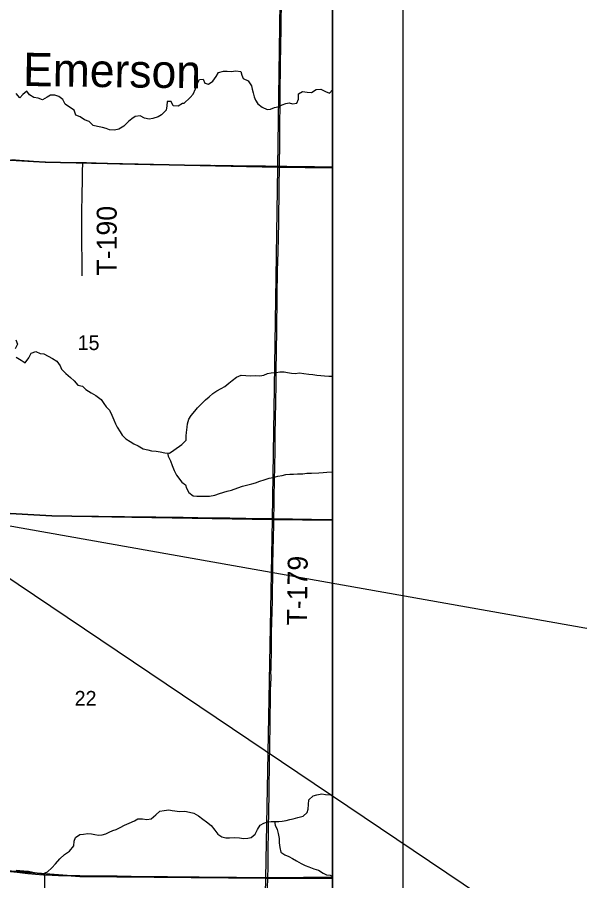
# Model space of a CAD drawing. Extents: x 0 to 34, y 0 to 22.
# Drawn here: x 8.451 to 9.252, y 18.765 to 19.994 of the extents above; entities that cross this region are included whole.
import ezdxf

# ---------------------------------------------------------------- set-up
doc = ezdxf.new("R2010")
doc.units = 0
for name, color, linetype in [('GM_X_Corporation', 7, 'Continuous'), ('GM_X_County_Road', 7, 'Continuous'), ('GM_X_Minor_River', 7, 'Continuous'), ('GM_X_Minor_River_Text', 7, 'Continuous'), ('GM_X_Section_Text', 7, 'Continuous'), ('GM_X_Township_Road', 7, 'Continuous'), ('GM_X_Township_Road_Text', 7, 'Continuous'), ('SH_Data', 7, 'Continuous'), ('SH_Text', 7, 'Continuous')]:
    doc.layers.add(name, color=color, linetype=linetype)

msp = doc.modelspace()

# ---------------------------------------------------------------- linework, layer by layer
at = {"layer": 'GM_X_Corporation'}
for points in [[(8.9, 14.1), (8.9, 20.772)], [(8.9, 17.776), (8.9, 20.772)]]:
    msp.add_lwpolyline(points, dxfattribs=at)
for points in [[(8.2996, 20.3033), (8.5044, 20.2865), (8.8288, 20.2829), (8.8217, 19.7804), (8.4905, 19.7876), (8.2906, 19.7989)], [(8.9, 19.7793), (8.9, 20.2818), (8.8288, 20.2829), (8.8217, 19.7804)], [(8.2906, 19.7989), (8.4905, 19.7876), (8.8217, 19.7804), (8.8138, 19.279), (8.5, 19.2839), (8.2875, 19.2957)], [(8.9, 19.2778), (8.9, 19.7793), (8.8217, 19.7804), (8.8138, 19.279)], [(8.2875, 19.2957), (8.5, 19.2839), (8.8138, 19.279), (8.8044, 18.7684), (8.5402, 18.7705), (8.2902, 18.7899)], [(8.9, 18.7679), (8.9, 19.2778), (8.8138, 19.279), (8.8044, 18.7684)], [(8.2902, 18.7899), (8.5402, 18.7705), (8.8044, 18.7684), (8.794, 18.271), (8.5238, 18.284), (8.2939, 18.2862)], [(8.9, 18.2696), (8.9, 18.7679), (8.8044, 18.7684), (8.794, 18.271)]]:
    msp.add_lwpolyline(points, close=True, dxfattribs=at)
at = {"layer": 'GM_X_County_Road'}
for points in [[(8.2874, 19.297), (8.3005, 19.2963), (8.3111, 19.2956), (8.3378, 19.294), (8.3989, 19.2902), (8.4417, 19.2875), (8.4867, 19.2848), (8.4988, 19.2844), (8.5215, 19.284), (8.5668, 19.2834), (8.6038, 19.2831), (8.6365, 19.2826), (8.6483, 19.2825), (8.6688, 19.2822), (8.6874, 19.282), (8.708, 19.2817), (8.7341, 19.2814), (8.7536, 19.2812), (8.7763, 19.2809), (8.8133, 19.2803), (8.8164, 19.2803)], [(8.8164, 19.2803), (8.8702, 19.2793), (8.8885, 19.279), (8.9, 19.2789)]]:
    msp.add_lwpolyline(points, dxfattribs=at)
at = {"layer": 'GM_X_Minor_River'}
for points in [[(8.6881, 19.8709), (8.6971, 19.8795), (8.7017, 19.8846), (8.705, 19.8922), (8.7073, 19.8992), (8.7103, 19.9054), (8.7156, 19.906), (8.7179, 19.8999), (8.7235, 19.8987), (8.7294, 19.9031), (8.7342, 19.9097), (8.7376, 19.9152), (8.7448, 19.9174), (8.7497, 19.9174), (8.7554, 19.9168), (8.7624, 19.9177), (8.7694, 19.9166), (8.7706, 19.9116), (8.7728, 19.9069), (8.78, 19.9034), (8.7845, 19.8964), (8.7854, 19.8916), (8.7869, 19.8861), (8.7884, 19.8808), (8.7901, 19.8761), (8.7937, 19.8705), (8.7999, 19.8658), (8.8067, 19.8627), (8.8118, 19.8632), (8.8175, 19.8653), (8.8223, 19.8664), (8.8285, 19.869), (8.8333, 19.8713), (8.8382, 19.8722), (8.8431, 19.8707), (8.8492, 19.8716), (8.8515, 19.8773), (8.8517, 19.8847), (8.8574, 19.8884), (8.864, 19.8875), (8.8701, 19.8869), (8.8767, 19.891), (8.8834, 19.8916), (8.89, 19.8883), (8.8958, 19.886), (8.9, 19.8906)], [(8.6881, 19.8709), (8.6864, 19.8709), (8.6801, 19.8672), (8.6731, 19.8676), (8.6701, 19.8742), (8.6642, 19.8739), (8.6638, 19.8678), (8.663, 19.8614), (8.6564, 19.855), (8.6516, 19.852), (8.6439, 19.8496), (8.6389, 19.849), (8.6323, 19.8502), (8.6259, 19.8536), (8.6189, 19.8524), (8.6141, 19.8492), (8.6092, 19.8454), (8.6025, 19.8388), (8.5955, 19.8348), (8.5893, 19.8332), (8.5823, 19.8338), (8.5774, 19.8357), (8.5723, 19.8371), (8.5651, 19.8384), (8.5589, 19.8396), (8.5532, 19.8457), (8.5466, 19.848), (8.5404, 19.852), (8.5345, 19.8543), (8.5317, 19.8614), (8.5255, 19.866), (8.5191, 19.8702), (8.5158, 19.8768), (8.5103, 19.881), (8.5042, 19.8828), (8.4982, 19.883), (8.4933, 19.8802), (8.487, 19.8764), (8.4806, 19.8789), (8.4743, 19.8797), (8.4683, 19.8837), (8.4644, 19.8885), (8.4589, 19.884), (8.4545, 19.8791), (8.4494, 19.8854)], [(8.4487, 19.5347), (8.4513, 19.5283), (8.4477, 19.5218)], [(8.4495, 19.5099), (8.4563, 19.5055), (8.4623, 19.5018), (8.4671, 19.5088), (8.4705, 19.5156), (8.4773, 19.5181), (8.4836, 19.5154), (8.4889, 19.5148), (8.5009, 19.5083), (8.5073, 19.5044), (8.5118, 19.4976)], [(8.5118, 19.4976), (8.5141, 19.4928), (8.5201, 19.4865), (8.5269, 19.4812), (8.5318, 19.4764), (8.537, 19.4701), (8.5438, 19.4686), (8.5487, 19.4638), (8.5563, 19.4592), (8.5629, 19.4556), (8.5702, 19.4495), (8.5743, 19.4439), (8.5777, 19.4392), (8.5822, 19.4344), (8.5856, 19.4276), (8.5886, 19.4209), (8.591, 19.4152), (8.5932, 19.4105), (8.5975, 19.4038), (8.6005, 19.3989), (8.6056, 19.3939), (8.6118, 19.3897), (8.6171, 19.3864), (8.623, 19.3836), (8.6301, 19.3795), (8.6371, 19.378), (8.642, 19.3768), (8.6487, 19.376), (8.6545, 19.3754), (8.6611, 19.3739), (8.6676, 19.3734), (8.6738, 19.3776), (8.6854, 19.3855)], [(8.6854, 19.3855), (8.6913, 19.3919), (8.6917, 19.3978), (8.6921, 19.4029), (8.6929, 19.4103), (8.6934, 19.415), (8.6954, 19.4216), (8.6986, 19.4269), (8.7037, 19.433), (8.7076, 19.4379), (8.7142, 19.4447), (8.7191, 19.4494), (8.7241, 19.4534), (8.7296, 19.4583), (8.7353, 19.4619), (8.7414, 19.4654), (8.7465, 19.4683), (8.7522, 19.4728), (8.7571, 19.4769), (8.7634, 19.4813), (8.7697, 19.4843), (8.7765, 19.484), (8.7837, 19.4836), (8.7909, 19.4838), (8.7965, 19.4836), (8.8022, 19.4843), (8.8074, 19.4866), (8.8127, 19.4877), (8.8197, 19.488), (8.8248, 19.4891), (8.831, 19.4893), (8.8361, 19.4883), (8.8416, 19.4873), (8.8467, 19.4868), (8.8528, 19.4875), (8.8591, 19.4869), (8.8664, 19.4857), (8.8721, 19.4851), (8.8778, 19.4843), (8.8833, 19.4841), (8.8884, 19.4835), (8.8946, 19.4829), (8.9, 19.4829)], [(8.6649, 19.3736), (8.6658, 19.3691), (8.669, 19.3624), (8.6714, 19.3556), (8.6742, 19.3488), (8.6778, 19.3421), (8.6851, 19.3321)], [(8.6851, 19.3321), (8.6906, 19.3283), (8.6918, 19.3234), (8.6953, 19.3171), (8.7014, 19.3127), (8.7065, 19.3121), (8.7116, 19.3119), (8.718, 19.3119), (8.7245, 19.3123), (8.7324, 19.3137), (8.7389, 19.3158), (8.7499, 19.3192), (8.7563, 19.3206), (8.7652, 19.324), (8.7719, 19.3261), (8.7776, 19.3276), (8.785, 19.3294), (8.7903, 19.3311), (8.7963, 19.3332), (8.8026, 19.3354), (8.8098, 19.3375), (8.8153, 19.3386), (8.8219, 19.3404), (8.8284, 19.3415), (8.8333, 19.3427), (8.839, 19.3434), (8.8443, 19.3436), (8.8502, 19.3437), (8.8577, 19.3441), (8.8636, 19.3446), (8.8699, 19.345), (8.8805, 19.3453), (8.8867, 19.3458), (8.8917, 19.3464), (8.9, 19.3467), (8.9, 19.3467)], [(8.6825, 18.8633), (8.6894, 18.8637), (8.6964, 18.8621), (8.7025, 18.8606), (8.7093, 18.8571), (8.7153, 18.8522), (8.7206, 18.8486), (8.7272, 18.843), (8.7323, 18.8367), (8.7366, 18.8308), (8.7425, 18.8272), (8.7478, 18.8255), (8.7534, 18.8255), (8.7599, 18.826), (8.7675, 18.8254), (8.7733, 18.8246), (8.7794, 18.8251), (8.7841, 18.8263), (8.79, 18.8306), (8.7931, 18.8374), (8.7967, 18.8437), (8.802, 18.8463), (8.8075, 18.8483), (8.8124, 18.8487), (8.8179, 18.8487), (8.8234, 18.849), (8.8283, 18.8492), (8.834, 18.8503), (8.839, 18.8518), (8.8441, 18.8527), (8.8507, 18.8546), (8.8581, 18.8564), (8.8638, 18.8615), (8.8653, 18.8665), (8.8656, 18.8731), (8.8665, 18.8795), (8.8724, 18.8856), (8.8777, 18.8867), (8.8849, 18.8882), (8.89, 18.8874), (8.897, 18.8868), (8.9, 18.8872)], [(8.4493, 18.7795), (8.4546, 18.7791), (8.4603, 18.7787), (8.4669, 18.7781), (8.4732, 18.7767), (8.48, 18.7753), (8.4873, 18.7745), (8.494, 18.777), (8.4999, 18.7828), (8.5052, 18.7885), (8.5115, 18.7955), (8.5183, 18.8017), (8.5252, 18.8066), (8.5315, 18.8141), (8.5321, 18.8211), (8.534, 18.8262), (8.5399, 18.8302), (8.5452, 18.8307), (8.5512, 18.8316), (8.5565, 18.8314), (8.5614, 18.8302), (8.5664, 18.8293), (8.5719, 18.8298), (8.577, 18.8315), (8.5819, 18.8337), (8.587, 18.8362), (8.5919, 18.8377), (8.5975, 18.8405), (8.6037, 18.8435), (8.6104, 18.8467), (8.6177, 18.8496), (8.6225, 18.8527), (8.6293, 18.8526), (8.6354, 18.8518), (8.6416, 18.8525), (8.6483, 18.8582), (8.6538, 18.8637), (8.66, 18.8646), (8.6666, 18.8657), (8.6717, 18.8643), (8.6825, 18.8633)], [(8.8175, 18.8487), (8.8185, 18.8435), (8.8213, 18.8373), (8.8226, 18.8318), (8.8239, 18.8248), (8.8241, 18.8185), (8.8248, 18.812), (8.8263, 18.8054), (8.8323, 18.8014), (8.8376, 18.7991), (8.8429, 18.7962), (8.8486, 18.7928), (8.8552, 18.7891), (8.861, 18.7863), (8.8665, 18.7842), (8.8735, 18.7817), (8.8798, 18.7797), (8.8866, 18.7753), (8.8915, 18.7729), (8.8966, 18.7726), (8.9, 18.7704)]]:
    msp.add_lwpolyline(points, dxfattribs=at)
at = {"layer": 'GM_X_Township_Road'}
for points in [[(8.8266, 19.9597), (8.8267, 19.9716), (8.827, 19.9884), (8.8273, 20.012), (8.8275, 20.036), (8.8284, 20.0816), (8.8293, 20.1373), (8.8302, 20.1848), (8.8307, 20.2056), (8.8314, 20.2454), (8.8319, 20.2846)], [(8.8246, 19.782), (8.8247, 19.7843), (8.8247, 19.792), (8.8248, 19.8054), (8.8249, 19.8172), (8.825, 19.8306), (8.825, 19.8387), (8.825, 19.8464), (8.8253, 19.8644), (8.8254, 19.8728), (8.8256, 19.8905), (8.8261, 19.921), (8.8266, 19.9592), (8.8266, 19.9597)], [(8.4431, 19.7913), (8.4539, 19.7906), (8.4678, 19.7896), (8.4839, 19.7882), (8.4911, 19.7879), (8.501, 19.7875), (8.5168, 19.7873), (8.5207, 19.7872)], [(8.5207, 19.7872), (8.5289, 19.787), (8.5401, 19.7869), (8.5441, 19.7869)], [(8.5431, 19.6259), (8.5431, 19.6306), (8.5432, 19.6399), (8.5432, 19.648), (8.5431, 19.6564), (8.543, 19.6633), (8.543, 19.6676), (8.543, 19.6754), (8.5429, 19.6806), (8.5429, 19.6855), (8.543, 19.6923), (8.543, 19.7016), (8.543, 19.7064), (8.543, 19.7151), (8.543, 19.7213), (8.543, 19.7272), (8.5431, 19.7303), (8.5431, 19.7343), (8.5435, 19.7489), (8.5436, 19.7548), (8.5436, 19.757), (8.5436, 19.7604), (8.544, 19.7768), (8.5441, 19.784), (8.5441, 19.7869)], [(8.5441, 19.7869), (8.5494, 19.7869), (8.5534, 19.7867), (8.5561, 19.7867), (8.5585, 19.7867), (8.5633, 19.7866), (8.574, 19.7863), (8.5771, 19.7862), (8.5796, 19.7861), (8.5848, 19.7859), (8.5919, 19.7856), (8.5972, 19.7854), (8.6131, 19.7851), (8.6183, 19.7849), (8.6273, 19.7848), (8.64, 19.7845), (8.6459, 19.7843), (8.6595, 19.7842), (8.6639, 19.7842), (8.6664, 19.7841), (8.6753, 19.7839), (8.6836, 19.7837), (8.6964, 19.7835), (8.7109, 19.7832), (8.7134, 19.7833), (8.7149, 19.7832), (8.7167, 19.7832), (8.7195, 19.7832), (8.7219, 19.7832), (8.7247, 19.7831), (8.7262, 19.7831), (8.7296, 19.783), (8.7321, 19.7831), (8.7345, 19.783), (8.7398, 19.7828), (8.7416, 19.7829), (8.7466, 19.7828), (8.7509, 19.7827), (8.7537, 19.7829), (8.7565, 19.7828), (8.7583, 19.7827), (8.7713, 19.7825), (8.7834, 19.7825), (8.8045, 19.7822), (8.8182, 19.7821), (8.8225, 19.782), (8.8246, 19.782)], [(8.8185, 19.4003), (8.8187, 19.4225), (8.8191, 19.4455), (8.8195, 19.4719), (8.8197, 19.489), (8.8202, 19.5192), (8.8205, 19.5481), (8.8212, 19.5966), (8.8218, 19.6335), (8.8224, 19.6596), (8.8233, 19.7019), (8.8242, 19.7513), (8.8246, 19.782)], [(8.8246, 19.782), (8.8294, 19.7819), (8.8347, 19.7818), (8.8468, 19.7816), (8.8567, 19.7815), (8.8718, 19.7814), (8.8745, 19.7813), (8.8803, 19.7811), (8.8837, 19.781), (8.8868, 19.781), (8.8895, 19.7809), (8.8935, 19.7809), (8.9, 19.7809)], [(8.8164, 19.2803), (8.8167, 19.2991), (8.817, 19.3125), (8.8173, 19.3327), (8.8178, 19.356), (8.8182, 19.375), (8.8184, 19.3818), (8.8184, 19.3886), (8.8185, 19.4003)], [(8.8078, 18.769), (8.8079, 18.7725), (8.8081, 18.7802), (8.8085, 18.8048), (8.8088, 18.8381), (8.8094, 18.8648), (8.8097, 18.8862), (8.8099, 18.9083), (8.8103, 18.9185), (8.8104, 18.9247), (8.8104, 18.9325), (8.8106, 18.9549), (8.8112, 18.9891), (8.8114, 19.0002), (8.8116, 19.0189), (8.8118, 19.02), (8.8117, 19.035), (8.8118, 19.0374), (8.812, 19.0436), (8.8124, 19.0542), (8.8123, 19.0623), (8.8124, 19.0644), (8.8124, 19.0653), (8.8125, 19.0686), (8.8125, 19.0704), (8.813, 19.0916), (8.8133, 19.1174), (8.8143, 19.163), (8.8145, 19.1733), (8.815, 19.2013), (8.8152, 19.2159), (8.8156, 19.2339), (8.8159, 19.2538), (8.8163, 19.2706), (8.8164, 19.2803)], [(8.2932, 18.7902), (8.2977, 18.7902), (8.3039, 18.7898), (8.3113, 18.7892), (8.32, 18.7886), (8.3386, 18.787), (8.3525, 18.7857), (8.3633, 18.7845), (8.3704, 18.7837), (8.3757, 18.7832), (8.3769, 18.7832), (8.3791, 18.783), (8.3816, 18.783), (8.3844, 18.783), (8.3912, 18.7828), (8.4005, 18.782), (8.4175, 18.7801), (8.4505, 18.7765), (8.4657, 18.7748), (8.4768, 18.7738), (8.4883, 18.773), (8.4899, 18.7729)], [(8.4899, 18.7729), (8.5004, 18.7724), (8.5097, 18.7722), (8.5265, 18.7719), (8.5402, 18.772), (8.5663, 18.7716), (8.5933, 18.7713), (8.6129, 18.7711), (8.6651, 18.7706), (8.7099, 18.7701), (8.7472, 18.7696), (8.7633, 18.7695), (8.8072, 18.769), (8.8078, 18.769)], [(8.4901, 18.6188), (8.49, 18.6269), (8.49, 18.6328), (8.4901, 18.6409), (8.49, 18.6698), (8.4902, 18.7118), (8.4901, 18.7407), (8.4901, 18.7575), (8.4901, 18.7659), (8.49, 18.7696), (8.4899, 18.7729)], [(8.7964, 18.2713), (8.7965, 18.2731), (8.797, 18.284), (8.7972, 18.2955), (8.7981, 18.3362), (8.7988, 18.3598), (8.7995, 18.3928), (8.8002, 18.4223), (8.8006, 18.44), (8.801, 18.4574), (8.8015, 18.4776), (8.802, 18.5006), (8.8027, 18.5373), (8.8036, 18.5746), (8.8046, 18.6175), (8.8053, 18.6563), (8.8059, 18.6858), (8.8064, 18.7088), (8.8068, 18.7266), (8.807, 18.7393), (8.8073, 18.753), (8.8078, 18.769)], [(8.8078, 18.769), (8.8168, 18.769), (8.8389, 18.7692), (8.8587, 18.7694), (8.8699, 18.7694), (8.8923, 18.7696), (8.8998, 18.7697), (8.9, 18.7697)]]:
    msp.add_lwpolyline(points, dxfattribs=at)
at = {"layer": 'SH_Data'}
for p, q in [((9, 21), (9, 14)), ((8.9, 20.9), (8.9, 14.1))]:
    msp.add_line(p, q, dxfattribs=at)
at = {"layer": 'SH_Text'}
msp.add_lwpolyline([(9.297, 18.6178), (8.2874, 19.297), (9.297, 19.1178)], close=True, dxfattribs=at)

# ---------------------------------------------------------------- texts
at = {"layer": 'GM_X_Minor_River_Text'}
msp.add_text('Emerson', height=0.04737, rotation=359.2115, dxfattribs=at).set_placement((8.4589, 19.8961))
at = {"layer": 'GM_X_Section_Text'}
for s, p in [('15', (8.5369, 19.5201)), ('22', (8.5326, 19.0138))]:
    msp.add_text(s, height=0.02093, rotation=0, dxfattribs=at).set_placement(p)
at = {"layer": 'GM_X_Township_Road_Text'}
for s, rotation, p in [('T-190', 90, (8.5925, 19.6261)), ('T-179', 89.1585, (8.8633, 19.1277))]:
    msp.add_text(s, height=0.02841, rotation=rotation, dxfattribs=at).set_placement(p)

doc.saveas('drawing.dxf')
